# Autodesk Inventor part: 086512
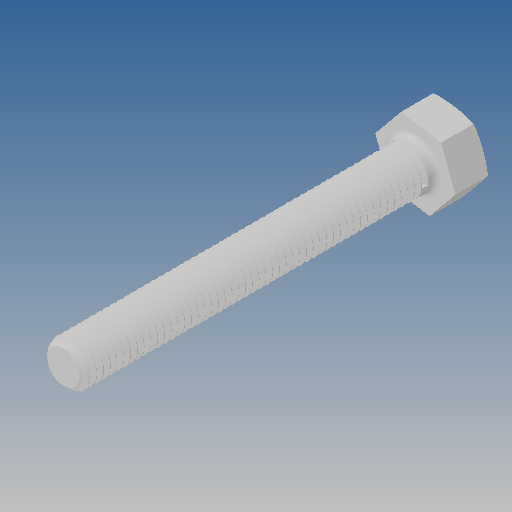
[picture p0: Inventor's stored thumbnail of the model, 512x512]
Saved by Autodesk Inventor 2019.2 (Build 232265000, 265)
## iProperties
Created: 2012-09
Part Number: 086512
Material: Ogólny
Document SubType Name: Modeling
Designer: CADENGINEERING4
Density: 1 g/cm^3
Appearance: Domyślna
Author: CADENGINEERING4
Revision Number: ÈÎºÎ
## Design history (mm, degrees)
feature "ÇÐ³ý-É¨Ãè1"
node "Bryła1"
